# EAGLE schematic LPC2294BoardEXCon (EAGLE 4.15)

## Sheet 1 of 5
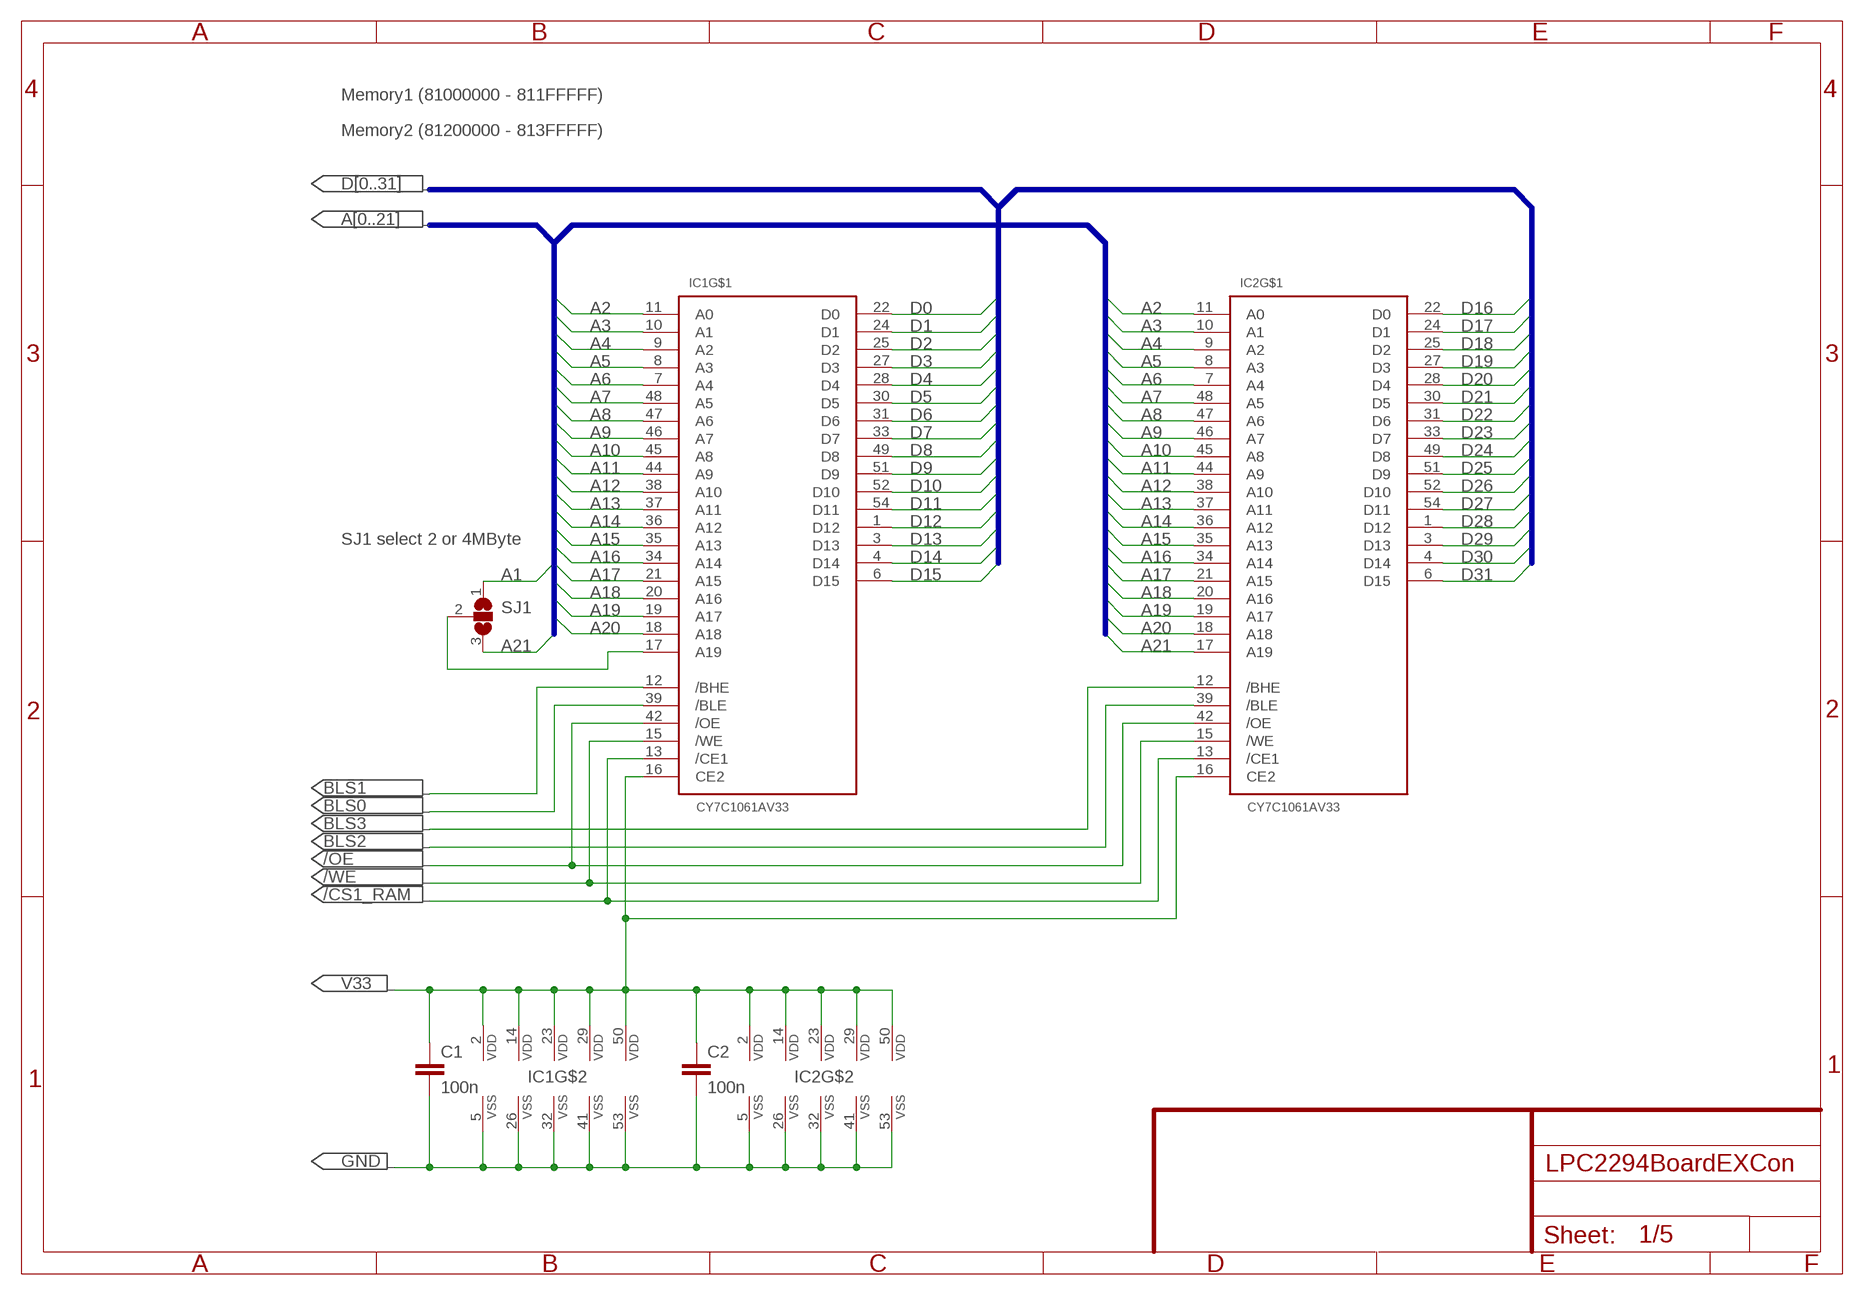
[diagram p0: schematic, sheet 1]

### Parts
C1  100n  C-EUC1206  [C1206]
C2  100n  C-EUC1206  [C1206]
IC1  CY7C1061AV33  [TSOPII54]
IC2  CY7C1061AV33  [TSOPII54]
SJ1  SJ2W  [SJ_2]

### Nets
/CS1_RAM: IC1.13(/CE1) IC2.13(/CE1) ; also sheet 2
/OE: IC1.42(/OE) IC2.42(/OE) ; also sheet 2,4,5
/WE: IC1.15(/WE) IC2.15(/WE) ; also sheet 2,4,5
A1: SJ1.1 ; also sheet 2,4,5
A2: IC1.11(A0) IC2.11(A0) ; also sheet 2,4,5
A3: IC1.10(A1) IC2.10(A1) ; also sheet 2,4,5
A4: IC1.9(A2) IC2.9(A2) ; also sheet 2,4,5
A5: IC1.8(A3) IC2.8(A3) ; also sheet 2
A6: IC1.7(A4) IC2.7(A4) ; also sheet 2
A7: IC1.48(A5) IC2.48(A5) ; also sheet 2
A8: IC1.47(A6) IC2.47(A6) ; also sheet 2
A9: IC1.46(A7) IC2.46(A7) ; also sheet 2
A10: IC1.45(A8) IC2.45(A8) ; also sheet 2
A11: IC1.44(A9) IC2.44(A9) ; also sheet 2
A12: IC1.38(A10) IC2.38(A10) ; also sheet 2
A13: IC1.37(A11) IC2.37(A11) ; also sheet 2
A14: IC1.36(A12) IC2.36(A12) ; also sheet 2
A15: IC1.35(A13) IC2.35(A13) ; also sheet 2
A16: IC1.34(A14) IC2.34(A14) ; also sheet 2
A17: IC1.21(A15) IC2.21(A15) ; also sheet 2
A18: IC1.20(A16) IC2.20(A16) ; also sheet 2
A19: IC1.19(A17) IC2.19(A17) ; also sheet 2
A20: IC1.18(A18) IC2.18(A18) ; also sheet 2
A21: IC2.17(A19) SJ1.3 ; also sheet 2
BLS0: IC1.39(/BLE) ; also sheet 2,5
BLS1: IC1.12(/BHE) ; also sheet 2,5
BLS2: IC2.39(/BLE) ; also sheet 2
BLS3: IC2.12(/BHE) ; also sheet 2
D0: IC1.22(D0) ; also sheet 2,4,5
D1: IC1.24(D1) ; also sheet 2,4,5
D2: IC1.25(D2) ; also sheet 2,4,5
D3: IC1.27(D3) ; also sheet 2,4,5
D4: IC1.28(D4) ; also sheet 2,4,5
D5: IC1.30(D5) ; also sheet 2,4,5
D6: IC1.31(D6) ; also sheet 2,4,5
D7: IC1.33(D7) ; also sheet 2,4,5
D8: IC1.49(D8) ; also sheet 2,5
D9: IC1.51(D9) ; also sheet 2,5
D10: IC1.52(D10) ; also sheet 2,5
D11: IC1.54(D11) ; also sheet 2,5
D12: IC1.1(D12) ; also sheet 2,5
D13: IC1.3(D13) ; also sheet 2,5
D14: IC1.4(D14) ; also sheet 2,5
D15: IC1.6(D15) ; also sheet 2,5
D16: IC2.22(D0) ; also sheet 2
D17: IC2.24(D1) ; also sheet 2
D18: IC2.25(D2) ; also sheet 2
D19: IC2.27(D3) ; also sheet 2
D20: IC2.28(D4) ; also sheet 2
D21: IC2.30(D5) ; also sheet 2
D22: IC2.31(D6) ; also sheet 2
D23: IC2.33(D7) ; also sheet 2
D24: IC2.49(D8) ; also sheet 2
D25: IC2.51(D9) ; also sheet 2
D26: IC2.52(D10) ; also sheet 2
D27: IC2.54(D11) ; also sheet 2
D28: IC2.1(D12) ; also sheet 2
D29: IC2.3(D13) ; also sheet 2
D30: IC2.4(D14) ; also sheet 2
D31: IC2.6(D15) ; also sheet 2
GND: C1.2 C2.2 IC1.5(VSS) IC1.26(VSS1) IC1.32(VSS2) IC1.41(VSS3) IC1.53(VSS4) IC2.5(VSS) IC2.26(VSS1) IC2.32(VSS2) IC2.41(VSS3) IC2.53(VSS4) ; also sheet 2,3,4,5
N$1: IC1.17(A19) SJ1.2
V33: C1.1 C2.1 IC1.2(VDD) IC1.14(VDD1) IC1.16(CE2) IC1.23(VDD2) IC1.29(VDD3) IC1.50(VDD4) IC2.2(VDD) IC2.14(VDD1) IC2.16(CE2) IC2.23(VDD2) IC2.29(VDD3) IC2.50(VDD4) ; also sheet 2,3,4,5

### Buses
A[0..21]
D[0..31]

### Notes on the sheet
- Memory1 (81000000 - 811FFFFF)
- Memory2 (81200000 - 813FFFFF)
- SJ1 select 2 or 4MByte

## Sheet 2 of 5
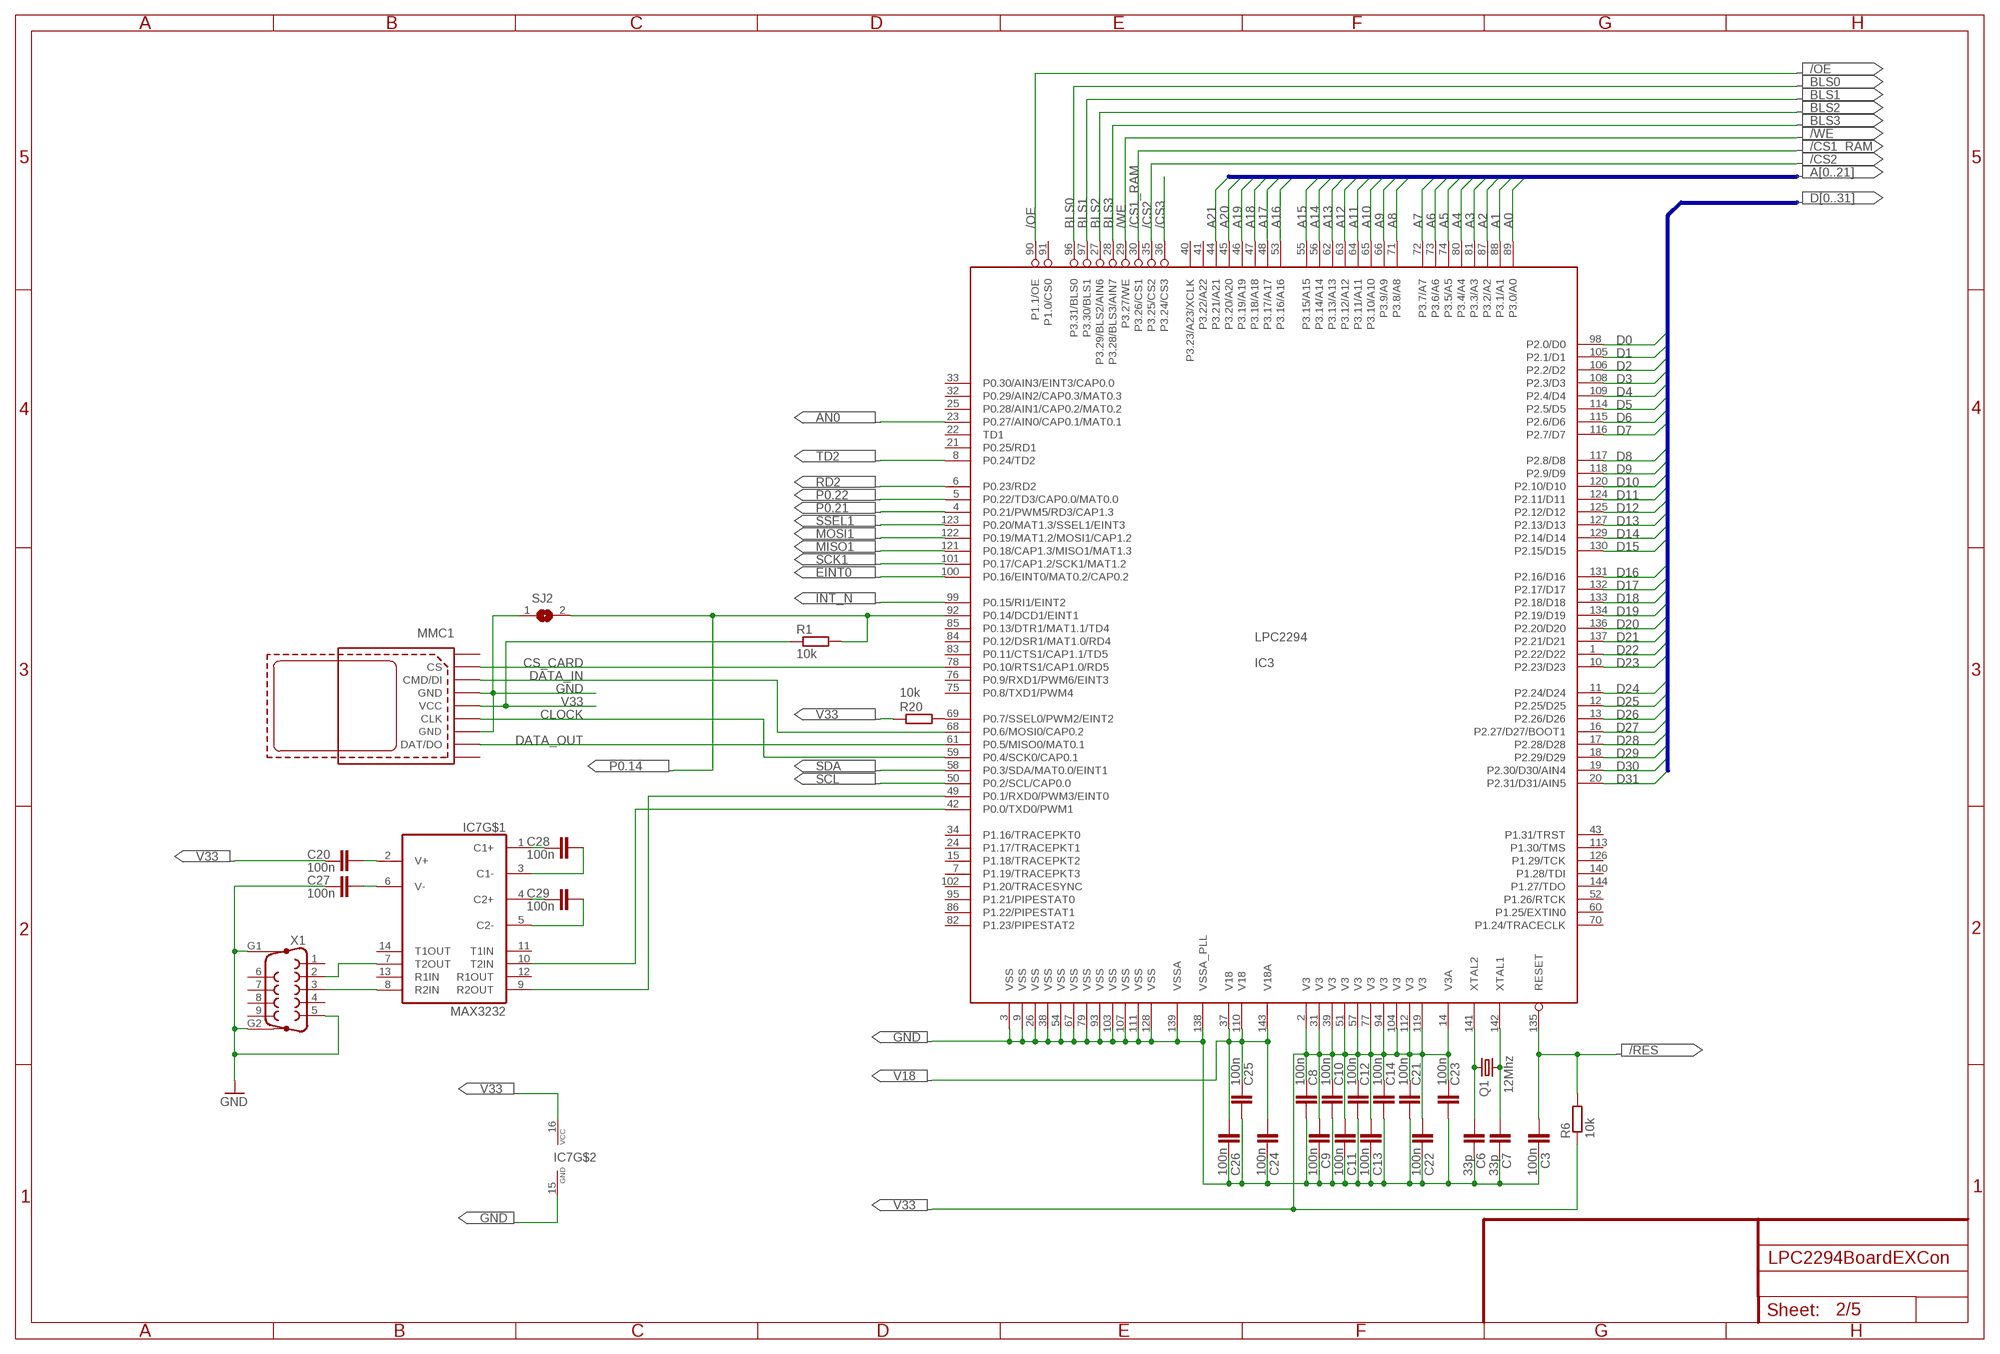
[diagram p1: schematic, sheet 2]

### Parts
C3  100n  C-EUC0805  [C0805]
C6  33p  C-EUC0805  [C0805]
C7  33p  C-EUC0805  [C0805]
C8  100n  C-EUC0805  [C0805]
C9  100n  C-EUC0805  [C0805]
C10  100n  C-EUC0805  [C0805]
C11  100n  C-EUC0805  [C0805]
C12  100n  C-EUC0805  [C0805]
C13  100n  C-EUC0805  [C0805]
C14  100n  C-EUC0805  [C0805]
C20  100n  C-EUC0805  [C0805]
C21  100n  C-EUC0805  [C0805]
C22  100n  C-EUC0805  [C0805]
C23  100n  C-EUC0805  [C0805]
C24  100n  C-EUC0805  [C0805]
C25  100n  C-EUC0805  [C0805]
C26  100n  C-EUC0805  [C0805]
C27  100n  C-EUC0805  [C0805]
C28  100n  C-EUC0805  [C0805]
C29  100n  C-EUC0805  [C0805]
IC3  LPC2294  [SOT486-1]
IC7  MAX3232  MAX202CSE  [SO16]
MMC1  SD_CARD  [SD9]
Q1  12Mhz  CRYTALHC49U-V  [HC49U-V]
R1  10k  R-EU_M0805  [M0805]
R6  10k  R-EU_R0603  [R0603]
R20  10k  R-EU_R0805  [R0805]
SJ2  SJ  [SJ]
X1  F09HP  [F09HP]

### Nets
/CS1_RAM: IC3.30(P3.26/CS1) ; also sheet 1
/CS2: IC3.35(P3.25/CS2) ; also sheet 4
/CS3: IC3.36(P3.24/CS3) ; also sheet 5
/OE: IC3.90(P1.1/OE) ; also sheet 1,4,5
/RES: C3.1 IC3.135(RESET) R6.2 ; also sheet 5
/WE: IC3.29(P3.27/WE) ; also sheet 1,4,5
A0: IC3.89(P3.0/A0) ; also sheet 4,5
A1: IC3.88(P3.1/A1) ; also sheet 1,4,5
A2: IC3.87(P3.2/A2) ; also sheet 1,4,5
A3: IC3.81(P3.3/A3) ; also sheet 1,4,5
A4: IC3.80(P3.4/A4) ; also sheet 1,4,5
A5: IC3.74(P3.5/A5) ; also sheet 1
A6: IC3.73(P3.6/A6) ; also sheet 1
A7: IC3.72(P3.7/A7) ; also sheet 1
A8: IC3.71(P3.8/A8) ; also sheet 1
A9: IC3.66(P3.9/A9) ; also sheet 1
A10: IC3.65(P3.10/A10) ; also sheet 1
A11: IC3.64(P3.11/A11) ; also sheet 1
A12: IC3.63(P3.12/A12) ; also sheet 1
A13: IC3.62(P3.13/A13) ; also sheet 1
A14: IC3.56(P3.14/A14) ; also sheet 1
A15: IC3.55(P3.15/A15) ; also sheet 1
A16: IC3.53(P3.16/A16) ; also sheet 1
A17: IC3.48(P3.17/A17) ; also sheet 1
A18: IC3.47(P3.18/A18) ; also sheet 1
A19: IC3.46(P3.19/A19) ; also sheet 1
A20: IC3.45(P3.20/A20) ; also sheet 1
A21: IC3.44(P3.21/A21) ; also sheet 1
AN0: IC3.23(P0.27/AIN0/CAP0.1/MAT0.1) ; also sheet 5
BLS0: IC3.96(P3.31/BLS0) ; also sheet 1,5
BLS1: IC3.97(P3.30/BLS1) ; also sheet 1,5
BLS2: IC3.27(P3.29/BLS2/AIN6) ; also sheet 1
BLS3: IC3.28(P3.28/BLS3/AIN7) ; also sheet 1
CLOCK: IC3.59(P0.4/SCK0/CAP0.1) MMC1.3(CLK)
CS_CARD: IC3.78(P0.10/RTS1/CAP1.0/RD5) MMC1.7(CS) ; also sheet 5
D0: IC3.98(P2.0/D0) ; also sheet 1,4,5
D1: IC3.105(P2.1/D1) ; also sheet 1,4,5
D2: IC3.106(P2.2/D2) ; also sheet 1,4,5
D3: IC3.108(P2.3/D3) ; also sheet 1,4,5
D4: IC3.109(P2.4/D4) ; also sheet 1,4,5
D5: IC3.114(P2.5/D5) ; also sheet 1,4,5
D6: IC3.115(P2.6/D6) ; also sheet 1,4,5
D7: IC3.116(P2.7/D7) ; also sheet 1,4,5
D8: IC3.117(P2.8/D8) ; also sheet 1,5
D9: IC3.118(P2.9/D9) ; also sheet 1,5
D10: IC3.120(P2.10/D10) ; also sheet 1,5
D11: IC3.124(P2.11/D11) ; also sheet 1,5
D12: IC3.125(P2.12/D12) ; also sheet 1,5
D13: IC3.127(P2.13/D13) ; also sheet 1,5
D14: IC3.129(P2.14/D14) ; also sheet 1,5
D15: IC3.130(P2.15/D15) ; also sheet 1,5
D16: IC3.131(P2.16/D16) ; also sheet 1
D17: IC3.132(P2.17/D17) ; also sheet 1
D18: IC3.133(P2.18/D18) ; also sheet 1
D19: IC3.134(P2.19/D19) ; also sheet 1
D20: IC3.136(P2.20/D20) ; also sheet 1
D21: IC3.137(P2.21/D21) ; also sheet 1
D22: IC3.1(P2.22/D22) ; also sheet 1
D23: IC3.10(P2.23/D23) ; also sheet 1
D24: IC3.11(P2.24/D24) ; also sheet 1
D25: IC3.12(P2.25/D25) ; also sheet 1
D26: IC3.13(P2.26/D26) ; also sheet 1
D27: IC3.16(P2.27/D27/BOOT1) ; also sheet 1
D28: IC3.17(P2.28/D28) ; also sheet 1
D29: IC3.18(P2.29/D29) ; also sheet 1
D30: IC3.19(P2.30/D30/AIN4) ; also sheet 1
D31: IC3.20(P2.31/D31/AIN5) ; also sheet 1
DATA_IN: IC3.68(P0.6/MOSI0/CAP0.2) MMC1.6(CMD/DI)
DATA_OUT: IC3.61(P0.5/MISO0/MAT0.1) MMC1.1(DAT/DO)
EINT0: IC3.100(P0.16/EINT0/MAT0.2/CAP0.2) ; also sheet 5
GND: C3.2 C6.2 C7.2 C8.2 C9.2 C10.2 C11.2 C12.2 C13.2 C14.2 C21.2 C22.2 C23.2 C24.2 C25.2 C26.2 C27.1 IC3.3(VSS) IC3.9(VSS) IC3.26(VSS) IC3.38(VSS) IC3.54(VSS) IC3.67(VSS) IC3.79(VSS) IC3.93(VSS) IC3.103(VSS) IC3.107(VSS) IC3.111(VSS) IC3.128(VSS) IC3.138(VSSA_PLL) IC3.139(VSSA) IC7.15(GND) MMC1.2(GND) MMC1.5(GND1) SJ2.1 X1.5 X1.G1 X1.G2 ; also sheet 1,3,4,5
INT_N: IC3.99(P0.15/RI1/EINT2) ; also sheet 4
MISO1: IC3.121(P0.18/CAP1.3/MISO1/MAT1.3) ; also sheet 5
MOSI1: IC3.122(P0.19/MAT1.2/MOSI1/CAP1.2) ; also sheet 5
N$5: IC3.69(P0.7/SSEL0/PWM2/EINT2) R20.2
N$6: C7.1 IC3.142(XTAL1) Q1.2
N$7: C6.1 IC3.141(XTAL2) Q1.1
N$8: IC3.42(P0.0/TXD0/PWM1) IC7.10(T2IN)
N$9: IC3.49(P0.1/RXD0/PWM3/EINT0) IC7.9(R2OUT)
N$19: C28.1 IC7.1(C1+)
N$20: C29.1 IC7.4(C2+)
N$21: C29.2 IC7.5(C2-)
N$22: C20.2 IC7.2(V+)
N$23: C27.2 IC7.6(V-)
N$24: IC7.7(T2OUT) X1.2
N$25: IC7.8(R2IN) X1.3
N$29: C28.2 IC7.3(C1-)
P0.14: IC3.92(P0.14/DCD1/EINT1) R1.2 SJ2.2 ; also sheet 5
P0.21: IC3.4(P0.21/PWM5/RD3/CAP1.3) ; also sheet 5
P0.22: IC3.5(P0.22/TD3/CAP0.0/MAT0.0) ; also sheet 5
RD2: IC3.6(P0.23/RD2) ; also sheet 5
SCK1: IC3.101(P0.17/CAP1.2/SCK1/MAT1.2) ; also sheet 5
SCL: IC3.50(P0.2/SCL/CAP0.0) ; also sheet 5
SDA: IC3.58(P0.3/SDA/MAT0.0/EINT1) ; also sheet 5
SSEL1: IC3.123(P0.20/MAT1.3/SSEL1/EINT3) ; also sheet 5
TD2: IC3.8(P0.24/TD2) ; also sheet 5
V18: C24.1 C25.1 C26.1 IC3.37(V18) IC3.110(V18) IC3.143(V18A) ; also sheet 3
V33: C8.1 C9.1 C10.1 C11.1 C12.1 C13.1 C14.1 C20.1 C21.1 C22.1 C23.1 IC3.2(V3) IC3.14(V3A) IC3.31(V3) IC3.39(V3) IC3.51(V3) IC3.57(V3) IC3.77(V3) IC3.94(V3) IC3.104(V3) IC3.112(V3) IC3.119(V3) IC7.16(VCC) MMC1.4(VCC) R1.1 R6.1 R20.1 ; also sheet 1,3,4,5
Unconnected: IC3.7(P1.19/TRACEPKT3) IC3.15(P1.18/TRACEPKT2) IC3.21(P0.25/RD1) IC3.22(TD1) IC3.24(P1.17/TRACEPKT1) IC3.25(P0.28/AIN1/CAP0.2/MAT0.2) IC3.32(P0.29/AIN2/CAP0.3/MAT0.3) IC3.33(P0.30/AIN3/EINT3/CAP0.0) IC3.34(P1.16/TRACEPKT0) IC3.40(P3.23/A23/XCLK) IC3.41(P3.22/A22) IC3.43(P1.31/TRST) IC3.52(P1.26/RTCK) IC3.60(P1.25/EXTIN0) IC3.70(P1.24/TRACECLK) IC3.75(P0.8/TXD1/PWM4) IC3.76(P0.9/RXD1/PWM6/EINT3) IC3.82(P1.23/PIPESTAT2) IC3.83(P0.11/CTS1/CAP1.1/TD5) IC3.84(P0.12/DSR1/MAT1.0/RD4) IC3.85(P0.13/DTR1/MAT1.1/TD4) IC3.86(P1.22/PIPESTAT1) IC3.91(P1.0/CS0) IC3.95(P1.21/PIPESTAT0) IC3.102(P1.20/TRACESYNC) IC3.113(P1.30/TMS) IC3.126(P1.29/TCK) IC3.140(P1.28/TDI) IC3.144(P1.27/TDO) IC7.11(T1IN) IC7.12(R1OUT) IC7.13(R1IN) IC7.14(T1OUT) MMC1.8(DAT1/RSV:8) MMC1.9(DAT2/RSV:9) MMC1.SW1 MMC1.SW2 MMC1.SW3 X1.1 X1.4 X1.6 X1.7 X1.8 X1.9

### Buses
D[0..31]
A[0..21]

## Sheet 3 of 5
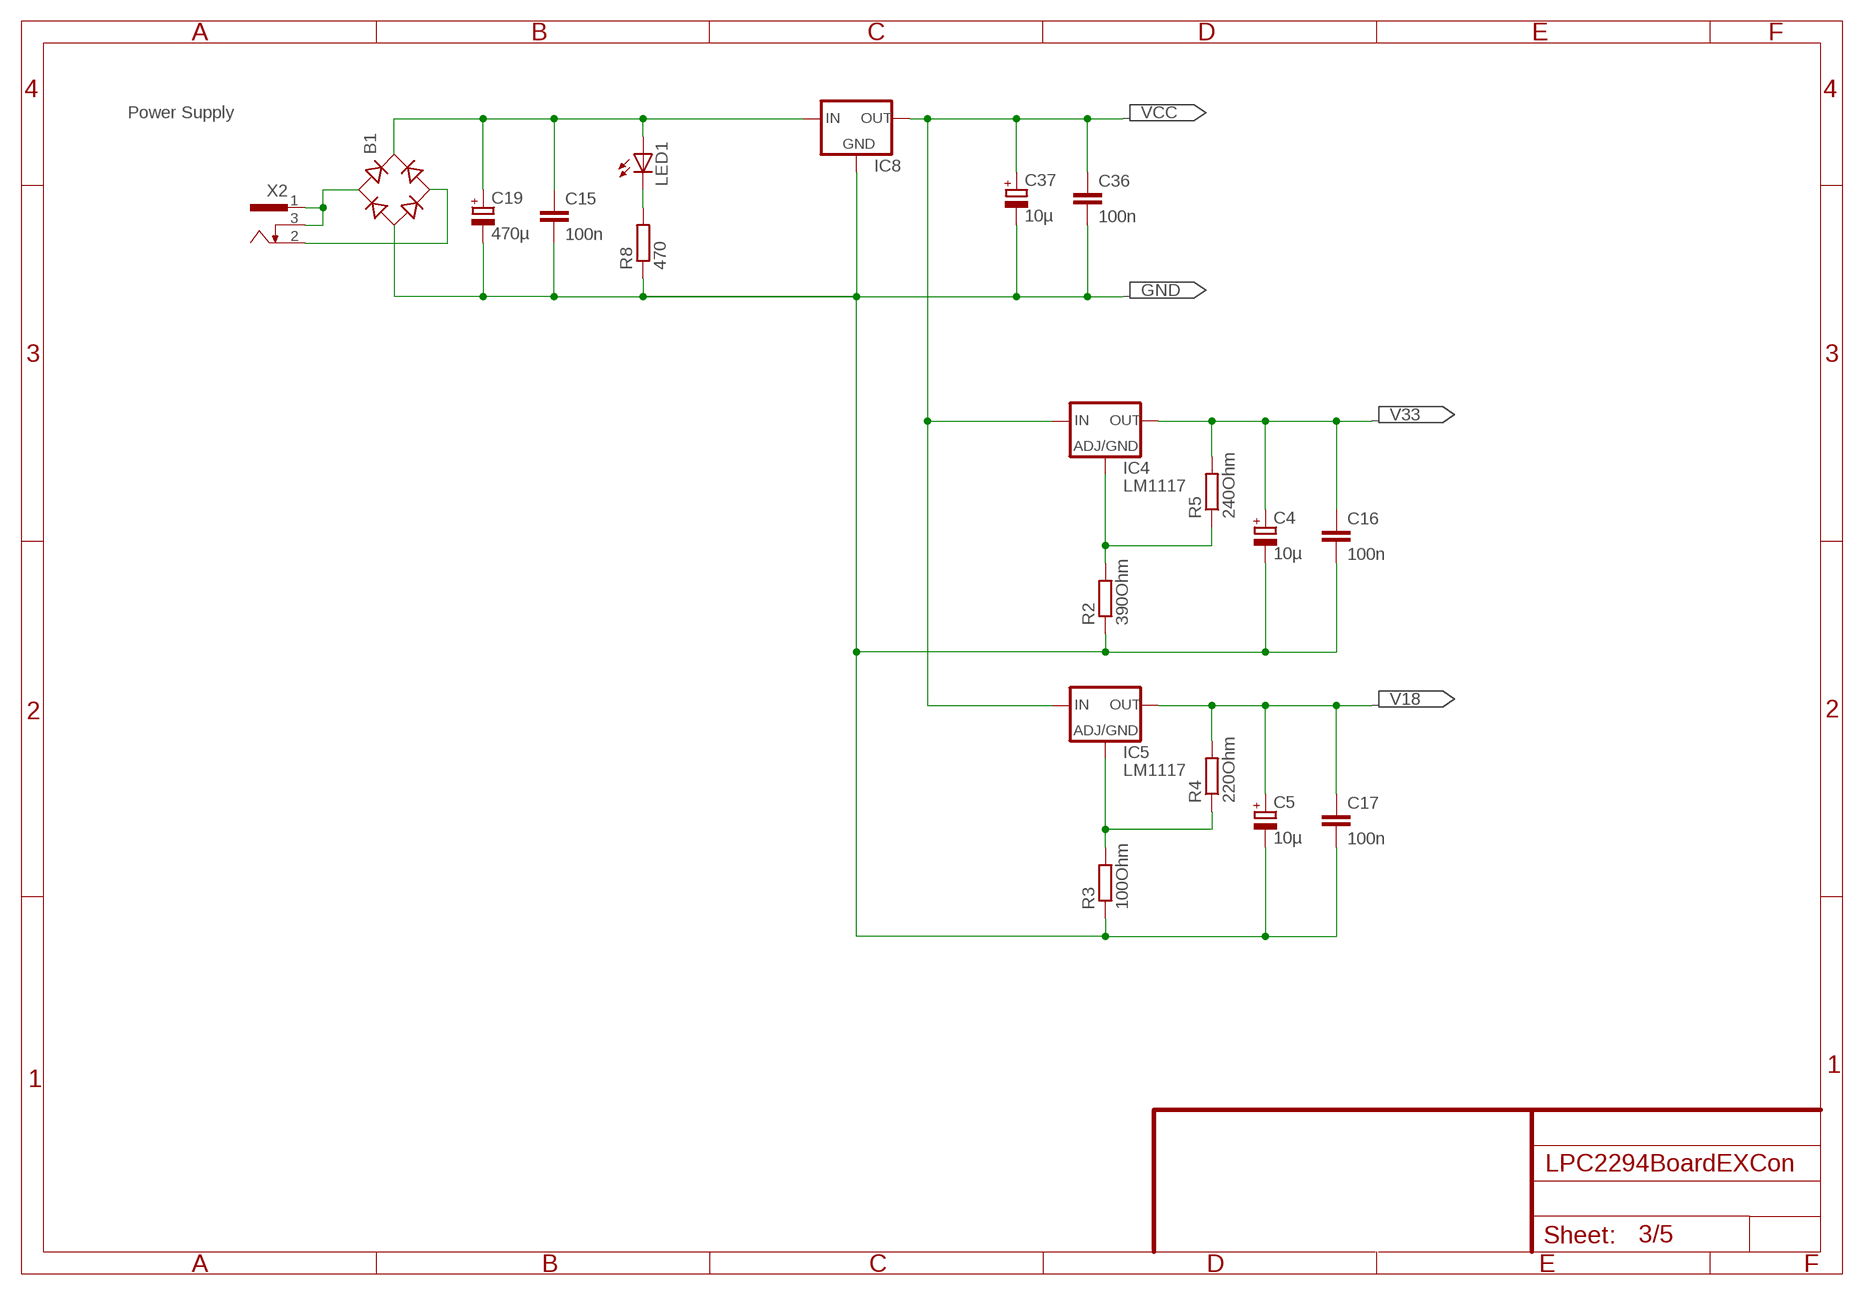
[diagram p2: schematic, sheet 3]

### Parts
B1  B-DIL  [B-DIL]
C4  10µ  CPOL-EUE2-5  [E2-5]
C5  10µ  CPOL-EUE2-5  [E2-5]
C15  100n  C-EUC1206  [C1206]
C16  100n  C-EUC1206  [C1206]
C17  100n  C-EUC1206  [C1206]
C19  470µ  CPOL-EUE5-8.5  [E5-8,5]
C36  100n  C-EUC1206  [C1206]
C37  10µ  CPOL-EUE2-5  [E2-5]
IC4  LM1117  LM1117SOT223  [SOT-233]
IC5  LM1117  LM1117SOT223  [SOT-233]
IC8  78XXL  [78XXL]
LED1  LEDP-LCC-2  [P-LCC-2]
R2  390Ohm  R-EU_M1206  [M1206]
R3  100Ohm  R-EU_M1206  [M1206]
R4  220Ohm  R-EU_M1206  [M1206]
R5  240Ohm  R-EU_M1206  [M1206]
R8  470  R-EU_M1206  [M1206]
X2  SCD-014A  [SCD-014-A]

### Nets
GND: B1.- C4.- C5.- C15.2 C16.2 C17.2 C19.- C36.2 C37.- IC8.GND R2.1 R3.1 R8.1 ; also sheet 1,2,4,5
N$2: LED1.C R8.2
N$12: IC4.1(ADJ/GND) R2.2 R5.1
N$17: IC5.1(ADJ/GND) R3.2 R4.1
N$31: B1.AC2 X2.2
N$32: B1.AC1 X2.1 X2.3
V18: C5.+ C17.1 IC5.2(OUT) R4.2 ; also sheet 2
V33: C4.+ C16.1 IC4.2(OUT) R5.2 ; also sheet 1,2,4,5
VCC: C36.1 C37.+ IC4.3(IN) IC5.3(IN) IC8.OUT ; also sheet 4,5
VIN: B1.+ C15.1 C19.+ IC8.IN LED1.A

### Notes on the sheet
- Power Supply

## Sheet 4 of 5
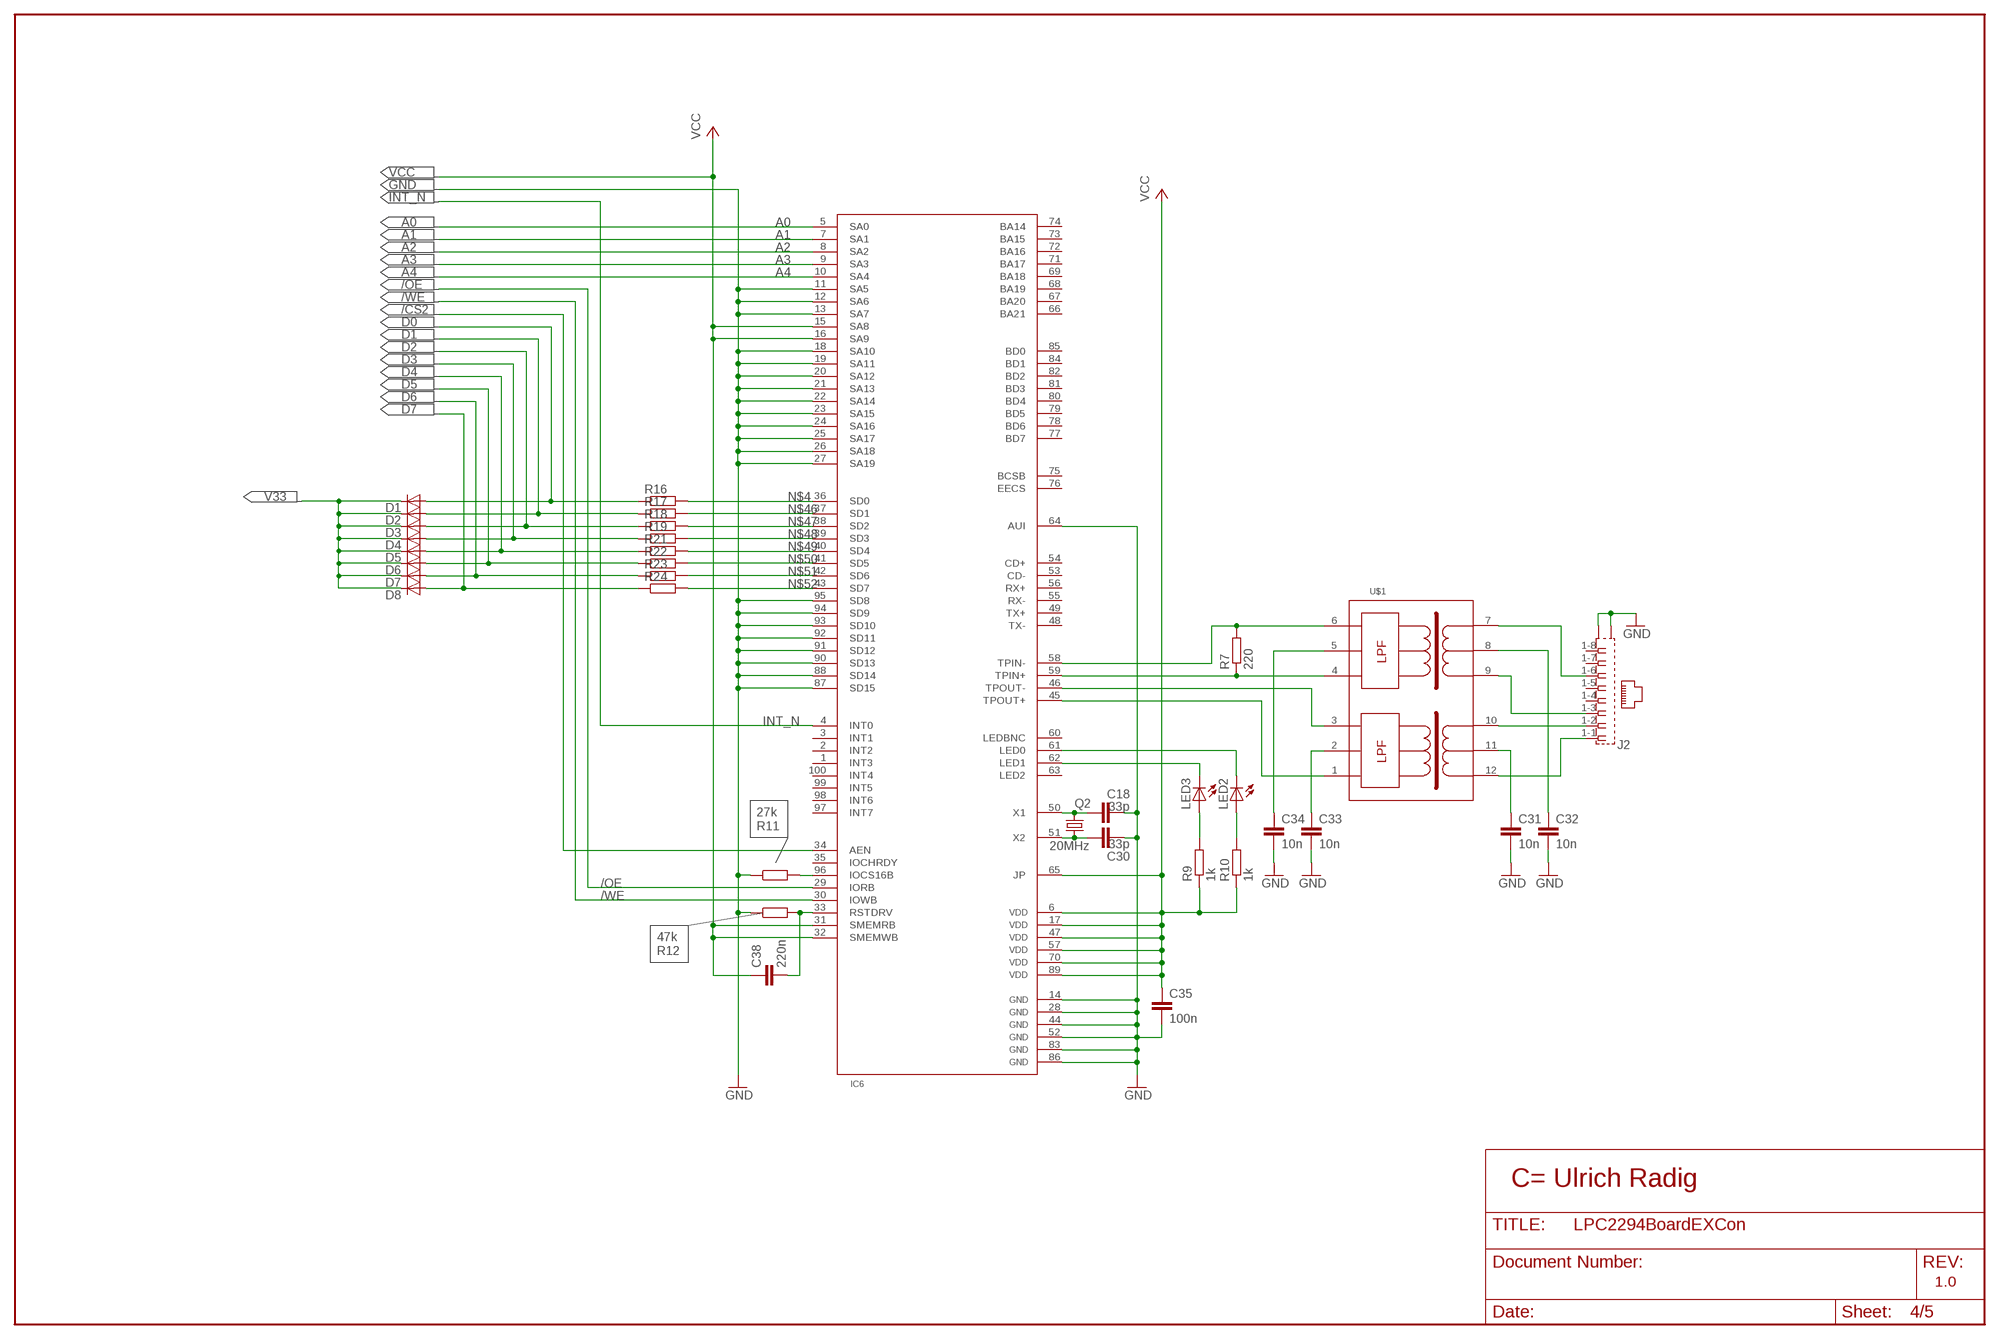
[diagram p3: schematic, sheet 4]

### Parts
C18  33p  C-EUC1206  [C1206]
C30  33p  C-EUC1206  [C1206]
C31  10n  C-EUC1206  [C1206]
C32  10n  C-EUC1206  [C1206]
C33  10n  C-EUC1206  [C1206]
C34  10n  C-EUC1206  [C1206]
C35  100n  C-EUC1206  [C1206]
C38  220n  C-EUC0805  [C0805]
D1  DIODE-MINIMELF  [MINIMELF]
D2  DIODE-MINIMELF  [MINIMELF]
D3  DIODE-MINIMELF  [MINIMELF]
D4  DIODE-MINIMELF  [MINIMELF]
D5  DIODE-MINIMELF  [MINIMELF]
D6  DIODE-MINIMELF  [MINIMELF]
D7  DIODE-MINIMELF  [MINIMELF]
D8  DIODE-MINIMELF  [MINIMELF]
IC6  RTL8019  [TQPF100]
J2  557786-1  [557786-1]
LED2  LEDP-LCC-2  [P-LCC-2]
LED3  LEDP-LCC-2  [P-LCC-2]
Q2  20MHz  CRYTALHC49S  [HC49/S]
R7  220  R-EU_R1206  [R1206]
R9  1k  R-EU_M1206  [M1206]
R10  1k  R-EU_M1206  [M1206]
R11  27k  R-EU_M1206  [M1206]
R12  47k  R-EU_R0805  [R0805]
R16  R-EU_M0805  [M0805]
R17  R-EU_M0805  [M0805]
R18  R-EU_M0805  [M0805]
R19  R-EU_M0805  [M0805]
R21  R-EU_M0805  [M0805]
R22  R-EU_M0805  [M0805]
R23  R-EU_M0805  [M0805]
R24  R-EU_M0805  [M0805]
U$1  20F001  [DIL16/12]

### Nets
/CS2: IC6.34(AEN) ; also sheet 2
/OE: IC6.29(IORB) ; also sheet 1,2,5
/WE: IC6.30(IOWB) ; also sheet 1,2,5
A0: IC6.5(SA0) ; also sheet 2,5
A1: IC6.7(SA1) ; also sheet 1,2,5
A2: IC6.8(SA2) ; also sheet 1,2,5
A3: IC6.9(SA3) ; also sheet 1,2,5
A4: IC6.10(SA4) ; also sheet 1,2,5
D0: D1.A R16.1 ; also sheet 1,2,5
D1: D2.A R17.1 ; also sheet 1,2,5
D2: D3.A R18.1 ; also sheet 1,2,5
D3: D4.A R19.1 ; also sheet 1,2,5
D4: D5.A R21.1 ; also sheet 1,2,5
D5: D6.A R22.1 ; also sheet 1,2,5
D6: D7.A R23.1 ; also sheet 1,2,5
D7: D8.A R24.1 ; also sheet 1,2,5
GND: C18.2 C30.2 C31.2 C32.2 C33.2 C34.2 C35.2 IC6.11(SA5) IC6.12(SA6) IC6.13(SA7) IC6.14(G1) IC6.18(SA10) IC6.19(SA11) IC6.20(SA12) IC6.21(SA13) IC6.22(SA14) IC6.23(SA15) IC6.24(SA16) IC6.25(SA17) IC6.26(SA18) IC6.27(SA19) IC6.28(G2) IC6.44(G3) IC6.52(G4) IC6.64(AUI) IC6.83(G5) IC6.86(G6) IC6.87(SD15) IC6.88(SD14) IC6.90(SD13) IC6.91(SD12) IC6.92(SD11) IC6.93(SD10) IC6.94(SD9) IC6.95(SD8) J2.G1(S2) J2.G2(S1) R11.1 R12.1 ; also sheet 1,2,3,5
INT_N: IC6.4(INT0) ; also sheet 2
N$4: IC6.36(SD0) R16.2
N$13: J2.1-1 U$1.12
N$14: J2.1-2 U$1.10
N$15: J2.1-3 U$1.9
N$16: J2.1-6 U$1.7
N$18: IC6.58(TPIN-) R7.2 U$1.6
N$26: IC6.59(TPIN+) R7.1 U$1.4
N$27: IC6.46(TPOUT-) U$1.3
N$28: IC6.45(TPOUT+) U$1.1
N$30: C33.1 U$1.2
N$33: C34.1 U$1.5
N$34: C31.1 U$1.11
N$35: C32.1 U$1.8
N$36: C18.1 IC6.50(X1) Q2.2
N$37: C30.1 IC6.51(X2) Q2.1
N$38: IC6.61(LED0) LED2.C
N$39: IC6.62(LED1) LED3.C
N$40: LED2.A R10.2
N$41: LED3.A R9.2
N$42: IC6.96(IOCS16B) R11.2
N$43: C38.2 IC6.33(RSTDRV) R12.2
N$46: IC6.37(SD1) R17.2
N$47: IC6.38(SD2) R18.2
N$48: IC6.39(SD3) R19.2
N$49: IC6.40(SD4) R21.2
N$50: IC6.41(SD5) R22.2
N$51: IC6.42(SD6) R23.2
N$52: IC6.43(SD7) R24.2
V33: D1.C D2.C D3.C D4.C D5.C D6.C D7.C D8.C ; also sheet 1,2,3,5
VCC: C35.1 C38.1 IC6.6(V1) IC6.15(SA8) IC6.16(SA9) IC6.17(V2) IC6.31(SMEMRB) IC6.32(SMEMWB) IC6.47(V3) IC6.57(V4) IC6.65(JP) IC6.70(V5) IC6.89(V6) R9.1 R10.1 ; also sheet 3,5
Unconnected: IC6.1(INT3) IC6.2(INT2) IC6.3(INT1) IC6.35(IOCHRDY) IC6.48(TX-) IC6.49(TX+) IC6.53(CD-) IC6.54(CD+) IC6.55(RX-) IC6.56(RX+) IC6.60(LEDBNC) IC6.63(LED2) IC6.66(BA21) IC6.67(BA20) IC6.68(BA19) IC6.69(BA18) IC6.71(BA17) IC6.72(BA16) IC6.73(BA15) IC6.74(BA14) IC6.75(BCSB) IC6.76(EECS) IC6.77(BD7) IC6.78(BD6) IC6.79(BD5) IC6.80(BD4) IC6.81(BD3) IC6.82(BD2) IC6.84(BD1) IC6.85(BD0) IC6.97(INT7) IC6.98(INT6) IC6.99(INT5) IC6.100(INT4) J2.1-4 J2.1-5 J2.1-7 J2.1-8

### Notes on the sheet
- C= Ulrich Radig
- 1.0

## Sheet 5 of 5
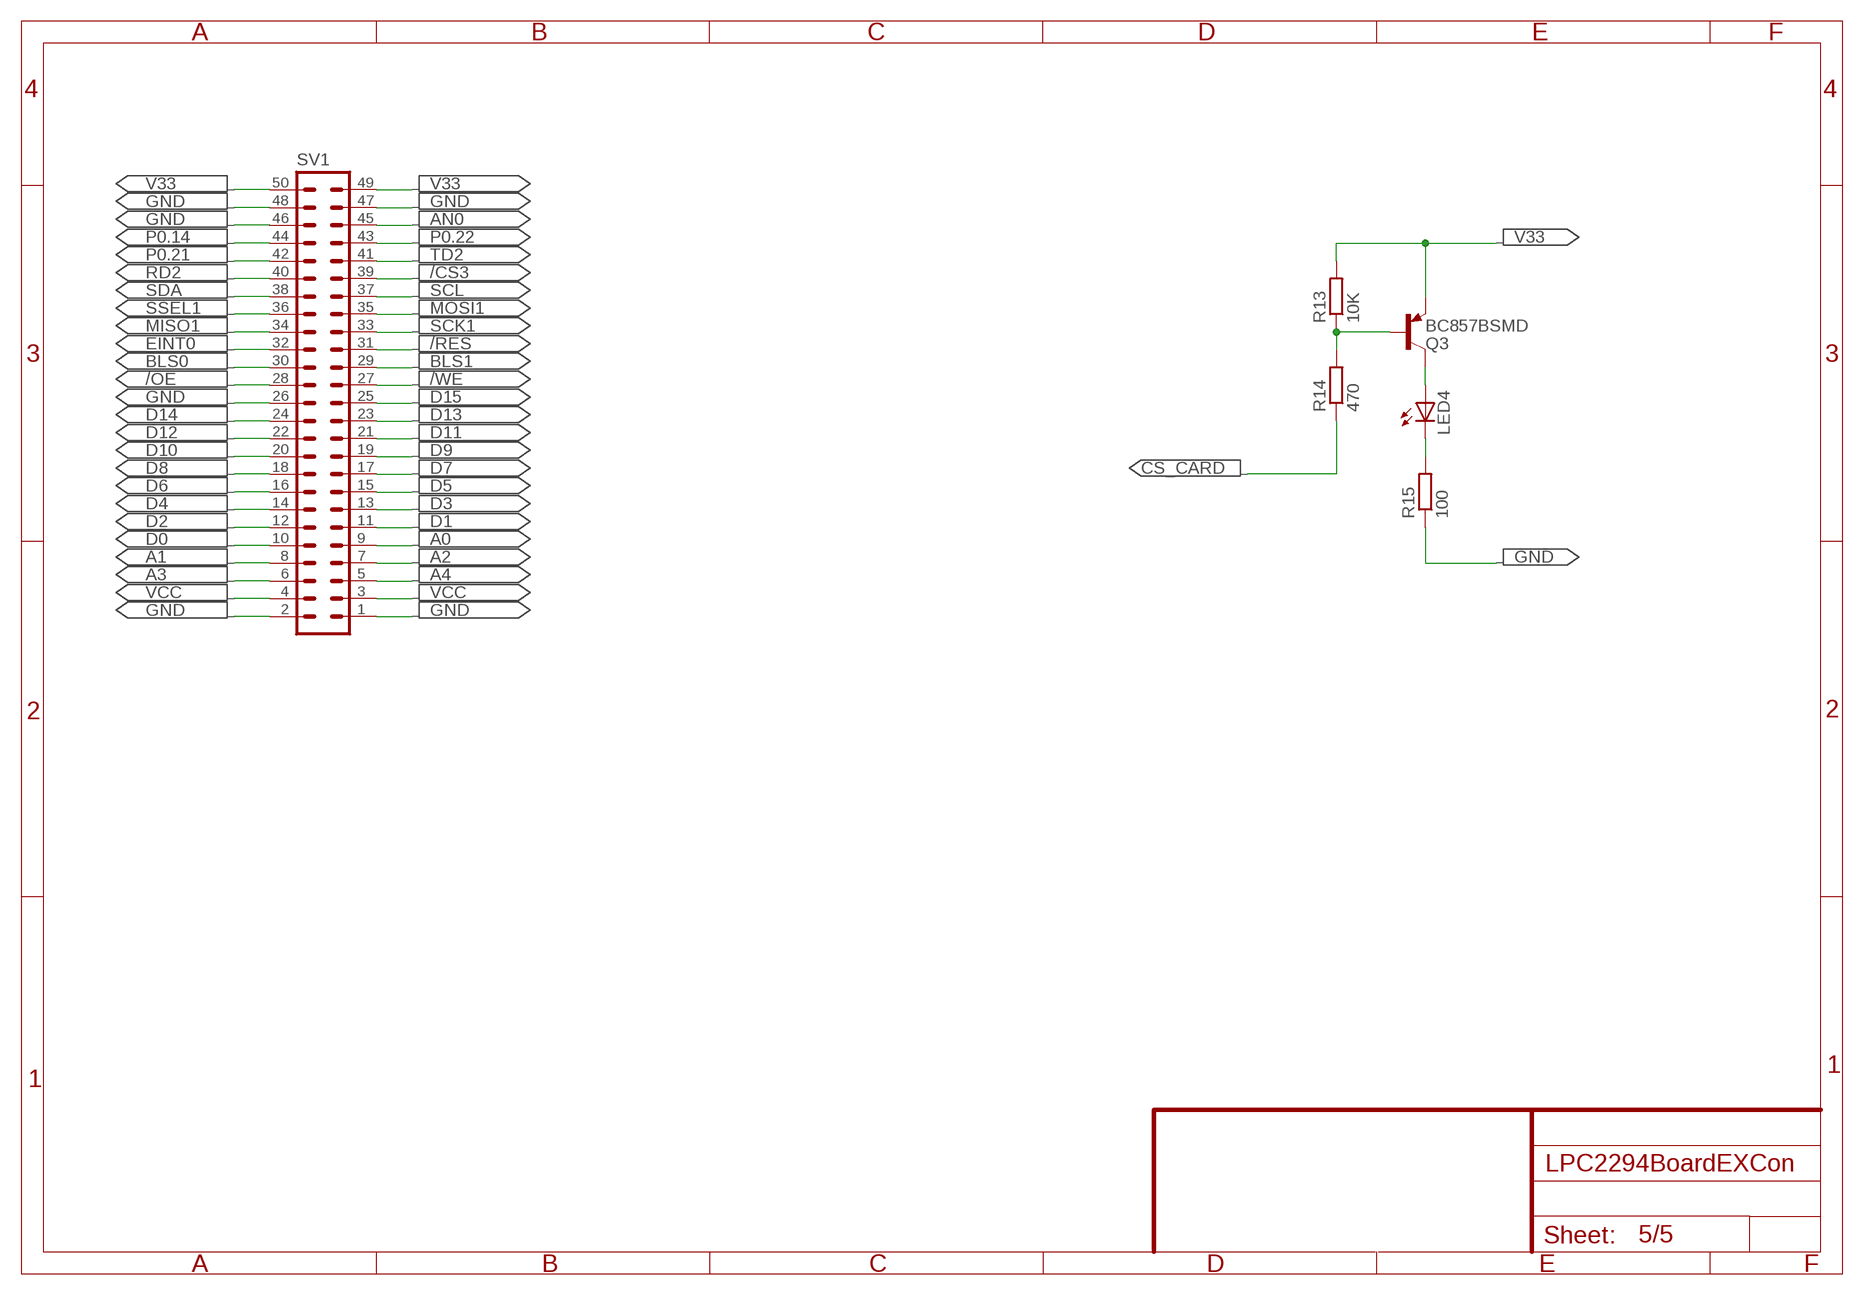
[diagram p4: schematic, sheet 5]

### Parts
LED4  LEDP-LCC-2  [P-LCC-2]
Q3  BC857BSMD  [SOT23-BEC]
R13  10K  R-EU_R1206  [R1206]
R14  470  R-EU_M0805  [M0805]
R15  100  R-EU_M0805  [M0805]
SV1  ML50  [ML50]

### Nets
/CS3: SV1.39 ; also sheet 2
/OE: SV1.28 ; also sheet 1,2,4
/RES: SV1.31 ; also sheet 2
/WE: SV1.27 ; also sheet 1,2,4
A0: SV1.9 ; also sheet 2,4
A1: SV1.8 ; also sheet 1,2,4
A2: SV1.7 ; also sheet 1,2,4
A3: SV1.6 ; also sheet 1,2,4
A4: SV1.5 ; also sheet 1,2,4
AN0: SV1.45 ; also sheet 2
BLS0: SV1.30 ; also sheet 1,2
BLS1: SV1.29 ; also sheet 1,2
CS_CARD: R14.1 ; also sheet 2
D0: SV1.10 ; also sheet 1,2,4
D1: SV1.11 ; also sheet 1,2,4
D2: SV1.12 ; also sheet 1,2,4
D3: SV1.13 ; also sheet 1,2,4
D4: SV1.14 ; also sheet 1,2,4
D5: SV1.15 ; also sheet 1,2,4
D6: SV1.16 ; also sheet 1,2,4
D7: SV1.17 ; also sheet 1,2,4
D8: SV1.18 ; also sheet 1,2
D9: SV1.19 ; also sheet 1,2
D10: SV1.20 ; also sheet 1,2
D11: SV1.21 ; also sheet 1,2
D12: SV1.22 ; also sheet 1,2
D13: SV1.23 ; also sheet 1,2
D14: SV1.24 ; also sheet 1,2
D15: SV1.25 ; also sheet 1,2
EINT0: SV1.32 ; also sheet 2
GND: R15.1 SV1.1 SV1.2 SV1.26 SV1.46 SV1.47 SV1.48 ; also sheet 1,2,3,4
MISO1: SV1.34 ; also sheet 2
MOSI1: SV1.35 ; also sheet 2
N$3: LED4.C R15.2
N$44: LED4.A Q3.C
N$45: Q3.B R13.1 R14.2
P0.14: SV1.44 ; also sheet 2
P0.21: SV1.42 ; also sheet 2
P0.22: SV1.43 ; also sheet 2
RD2: SV1.40 ; also sheet 2
SCK1: SV1.33 ; also sheet 2
SCL: SV1.37 ; also sheet 2
SDA: SV1.38 ; also sheet 2
SSEL1: SV1.36 ; also sheet 2
TD2: SV1.41 ; also sheet 2
V33: Q3.E R13.2 SV1.49 SV1.50 ; also sheet 1,2,3,4
VCC: SV1.3 SV1.4 ; also sheet 3,4

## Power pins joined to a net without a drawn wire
GND1: MMC1.G1(GND1)
GND2: MMC1.G2(GND2)
GND3: MMC1.G3(GND3)
GND4: MMC1.G4(GND4)
GND5: MMC1.G5(GND5)
GND6: MMC1.G6(GND6)
GND7: MMC1.G7(GND7)

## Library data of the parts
B1 = rectifier:B-DIL: RECTIFIER
C1-C3 C6-C18 C20-C36 C38 = rcl:C-EU: CAPACITOR, European symbol
C4 C5 C19 C37 = rcl:CPOL-EU: POLARIZED CAPACITOR, European symbol
D1-D8 = diode:DIODE-: DIODE
IC1 IC2 = Cypress-SRAM:CY7C1061AV33
IC3 = Philips_LPC2XXX:LPC2294
IC4 IC5 = LM1117:LM1117
IC6 = Realtek:RTL8019
IC7 = maxim:MAX202CSE
IC8 = v-reg:78XXL: VOLTAGE REGULATOR
J2 = con-amp:557786-1: AMP CONNECTOR
LED1-LED4 = led:LED: LED
MMC1 = sd_card:SD_CARD: Farnell / Order Code: 4381610 http://www.farnell.com/datasheets/37839.pdf kingfont Precision Industrial co., LTD. Secure Digital Memory Card Push-Push connector type B Changes by Guido Fischer - 29.12.2004 www.ispf.de by André Mansur - Brazil - 19/11/2004
Q1 Q2 = crystal:CRYTAL: CRYSTAL
Q3 = transistor-pnp:BC857*: PNP Transistror
R1-R24 = rcl:R-EU_: RESISTOR, European symbol
SJ1 = jumper:SJ2W: SMD solder JUMPER
SJ2 = jumper:SJ: SMD solder JUMPER
SV1 = con-harting-ml:ML50: HARTING
U$1 = Realtek:20F001
X1 = con-subd:F09HP: SUB-D
X2 = con-shiua-chyuan:SCD-014A: Power Jack 2.5mm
